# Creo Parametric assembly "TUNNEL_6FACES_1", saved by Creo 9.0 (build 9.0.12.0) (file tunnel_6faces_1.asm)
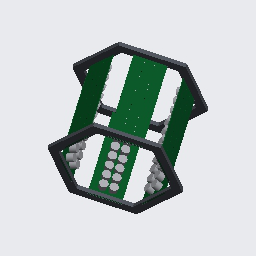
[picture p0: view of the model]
Units: millimeter Newton Second (mmNs); MM, TONNE, SECS

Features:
  1. coordinate system "TUNNEL_6FACES_1"
  2. imported feature "Import Feature id 4"
  3. component "PANEL_6F_01"
  4. component "PANEL_6F_02"
  5. component
  6. component
  7. component
  8. component
  9. component
  10. component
